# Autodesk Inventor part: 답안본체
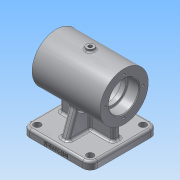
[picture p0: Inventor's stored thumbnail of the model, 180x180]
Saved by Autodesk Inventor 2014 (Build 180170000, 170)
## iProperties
Created: 2019-06
Part Number: 답안본체
Material: 알루미늄 6061
Document SubType Name: Modeling
Designer: NET
Density: 2.71 g/cm^3
Appearance: 알루미늄 - 평지
Mass: 612.698 g
Surface Area: 622.652 cm^2
Volume: 226.088 cm^3
Author: NET
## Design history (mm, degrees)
sketch "스케치1"
  geometry: L1 (45, 0)-(-45, 0); L2 (45, 0)-(45, 32); L3 (45, 32)-(-45, 32); L4 (-45, 32)-(-45, 0); L5 (45, 20)-(30.6, 20); L6 (30, 19.4)-(30, 17); L7 (30, 17)-(24, 17); L8 (24, 17)-(24, 22); L9 (21, 25)-(-21, 25); L10 (-24, 22)-(-24, 17); L11 (-24, 17)-(-30, 17); L12 (-30, 17)-(-30, 19.4); L13 (-30.6, 20)-(-45, 20); A1 r 0.6 centre (30.6, 19.4) between (30.6, 20) and (30, 19.4); A2 r 0.6 centre (-30.6, 19.4) between (-30, 19.4) and (-30.6, 20); A3 r 3 centre (21, 22) between (24, 22) and (21, 25); A4 r 3 centre (-21, 22) between (-21, 25) and (-24, 22); 5 further points
  constraints: 26 end point, 8 point on circle, 8 point on line, 8 tangent, 7 parallel, 5 perpendicular, 4 centre point, 2 equal radius, 1 coincident, 1 horizontal, 1 midpoint
  dimensions: "d0" = 90 distance of L1.start L1.end; "d1" = 64 diameter of L3 L1; "d2" = 48 distance of point (24, 25) point (-24, 25); "d3" = 50 diameter of L9 L1; "d4" = 15 distance of L5.start point (30, 20); "d5" = 40 diameter of L5 L1; "d6" = 34 diameter of L7 L1; "d7" = 6 distance of L6.end L7.end; "d8" = 6 distance of L10.end L11.end; "d9" = 34 diameter of L11 L1; "d10" = 40 diameter of L13 L1; "d11" = 0.6 radius of A1; "d12" = 3 radius of A3
revolve "회전1" sketch "스케치1" stored, may be unused: angle "d13" = 90 deg
chamfer "모따기1" distance "d14" = 1; stored, may be unused: second distance "d15" = 2, angle "d16" = 45 deg
node "작업 평면1"
sketch "스케치2"
  geometry: C1 r 5 at (0, 0); 1 further point
  constraints: 1 centre point, 1 coincident
  dimensions: "d18" = 10 diameter of C1
extrude "돌출1" join sketch "스케치2" stored distance "d19" = 10; taper "d20" = 0 deg
sketch "스케치3"
  geometry: C1 r 5 at (0, 0) reference; 1 further point
  constraints: 1 coincident
hole "구멍1" sketch "스케치3" at (0, 0) diameter "d21" = 4.917; stored, may be unused: countersink angle "d25" = 90 deg, drill point angle "d27" = 118 deg; dims "d22" = 6, "d23" = 4, "d24" = 2, "d26" = 20
fillet "모깎기1" dims "d28" = 2
node "작업 평면2"
sketch "스케치4"
  geometry: L1 (-45, -45)-(45, -45); L2 (45, -45)-(45, 45); L3 (45, 45)-(-45, 45); L4 (-45, 45)-(-45, -45); L5 (-45, -45)-(45, 45); L6 (45, -45)-(-45, 45); 1 further point
  constraints: 12 end point, 2 midpoint, 2 parallel, 1 horizontal, 1 perpendicular
  dimensions: "d30" = 90 distance of L2.end L3.end; "d31" = 90 distance of L1.end L2.end
extrude "돌출2" join sketch "스케치4" distance "d32" = 10; taper "d33" = 0 deg
fillet "모깎기2" dims "d34" = 10
fillet "모깎기3" dims "d35" = 3
sketch "스케치5"
  geometry: L1 (-35, -5)-(35, -5); L2 (35, -5)-(35, 5); L3 (35, 5)-(-35, 5); L4 (-35, 5)-(-35, -5); L5 (-35, -5)-(35, 5); L6 (35, -5)-(-35, 5); 1 further point
  constraints: 12 end point, 2 midpoint, 2 parallel, 1 horizontal, 1 perpendicular
  dimensions: "d36" = 10 distance between parallel lines of L3 L1; "d37" = 70 distance of L1.start L1.end
extrude "돌출3" join sketch "스케치5" stored distance "d38" = 10; taper "d39" = 0 deg
sketch "스케치6"
  geometry: L1 (45, -58)-(45, -65) reference; L2 (45, -65)-(-45, -65) reference; L3 (-45, -65)-(-45, -58) reference; L4 (-42, -55)-(-5, -55) reference; L5 (-5, -55)-(-5, -31.607) reference; L6 (-5, 33.272)-(-5, 35) reference; L7 (-5, 35)-(-2.458, 35) reference; L8 (-2.458, 35)-(-2.458, 24.879) reference; L9 (2.458, 24.879)-(2.458, 35) reference; L10 (2.458, 35)-(5, 35) reference; L11 (5, 35)-(5, 33.272) reference; L12 (5, -31.607)-(5, -55) reference; L13 (5, -55)-(42, -55) reference; L14 (-35, -55)-(-23.058, -22.189); A1 r 3 centre (42, -58) between (45, -58) and (42, -55) reference; A2 r 3 centre (-42, -58) between (-42, -55) and (-45, -58) reference; A3 r 32 centre (0, 0) between (-6.588, 31.314) and (-5, -31.607) reference; A4 r 25 centre (0, 0) between (-2.458, 24.879) and (2.458, 24.879) reference; A5 r 32 centre (0, 0) between (5, -31.607) and (6.588, 31.314) reference; 1 further point
  constraints: 2 end point, 1 point on circle, 1 point on line, 2 other
  dimensions: "d41" = 110 deg angle of L4 L14; "d42" = 10 distance from line of L14.start L3
feature "리브1" sketch "스케치6" dims "d43" = 1, "d44" = 10, "d45" = 0, "d46" = 0, "d47" = 1, "d48" = 1
fillet "모깎기4" dims "d49" = 3
fillet "모깎기5" dims "d50" = 3
fillet "모깎기6" dims "d51" = 3
fillet "모깎기7" dims "d52" = 3
fillet "모깎기8" dims "d53" = 3
fillet "모깎기9" dims "d54" = 3
fillet "모깎기10" dims "d55" = 3
fillet "모깎기11" dims "d56" = 3
fillet "모깎기12" dims "d57" = 3
sketch "스케치7"
  geometry: C1 r 4.5 at (-35, 35); C2 r 4.5 at (-35, -35); A1 r 7 centre (-35, 35) between (-35, 42) and (-42, 35) reference; A2 r 7 centre (-35, -35) between (-42, -35) and (-35, -42) reference; 1 further point
  constraints: 2 centre point, 2 coincident
  dimensions: "d58" = 9 diameter of C1; "d59" = 9 diameter of C2
extrude "돌출4" cut sketch "스케치7" distance "d60" = 35; taper "d61" = 0 deg
sketch "스케치8"
  geometry: C1 r 32 at (0, 0) reference; 1 further point
  constraints: 1 horizontal alignment
  dimensions: "d63" = 25 distance of C1.centre point (-25, 0)
hole "구멍2" sketch "스케치8" at (-25, 0) diameter "d64" = 3.242; stored, may be unused: countersink angle "d68" = 90 deg, drill point angle "d70" = 118 deg; dims "d65" = 7, "d66" = 4, "d67" = 2, "d69" = 9
sketch "스케치9"
  geometry: L1 (0, 0)-(70, 0) reference; L2 (-10, 7)-(-10, 0) reference; 2 further points
  constraints: 1 other
  dimensions: "d74" = 4 distance from line of point (35, 4) L1; "d75" = 45 distance from line of point (35, 4) L2
feature "엠보싱1" sketch "스케치9" dims "d0" = 90, "d1" = 64, "d2" = 48, "d3" = 50, "d4" = 15, "d5" = 40, "d6" = 34, "d7" = 6, "d8" = 6, "d9" = 34, "d10" = 40, "d11" = 0.6, "d12" = 3, "d76" = 0.5, "d77" = 0
sketch "스케치10" dims "d80" = 20
  geometry: L1 (35, -45)-(-35, -45) reference; L2 (45, 35)-(45, -35) reference; L3 (-22, -40)-(22, -40); L4 (40, -22)-(40, 22); L5 (-40, 22)-(-40, -22); L6 (-40, -40)-(40, 40); L7 (40, -40)-(-40, 40); L8 (-25, -37)-(-25, -35); L9 (-37, -25)-(-35, -25); L10 (-37, 25)-(-35, 25); L11 (-25, 35)-(-25, 37); L12 (22, 40)-(-22, 40); L13 (-26.34, 40)-(-40, 40); L14 (25, 37)-(25, 35); L15 (35, 25)-(37, 25); L16 (25, -37)-(25, -35); L17 (35, -25)-(37, -25); C1 r 10 at (35, 35); C2 r 10 at (-35, -35); C3 r 10 at (35, -35); A1 r 10 centre (35, -35) between (35, -45) and (45, -35) reference; A2 r 10 centre (35, 35) between (45, 35) and (35, 45) reference; A3 r 10 centre (-35, 35) between (-35, 45) and (-45, 35) reference; A4 r 10 centre (-35, -35) between (-45, -35) and (-35, -45) reference; A5 r 10 centre (-35, 35) between (-35, 25) and (-25, 35); A6 r 10 centre (35, 35) between (25, 35) and (35, 25); A7 r 10 centre (35, -35) between (35, -25) and (25, -35); A8 r 10 centre (-35, -35) between (-25, -35) and (-35, -25); A9 r 3 centre (-37, -22) between (-40, -22) and (-37, -25); A10 r 3 centre (-22, -37) between (-25, -37) and (-22, -40); A11 r 3 centre (37, 22) between (40, 22) and (37, 25); A12 r 3 centre (22, 37) between (25, 37) and (22, 40); A13 r 3 centre (-37, 22) between (-37, 25) and (-40, 22); A14 r 3 centre (-22, 37) between (-22, 40) and (-25, 37); A15 r 3 centre (37, -22) between (37, -25) and (40, -22); A16 r 3 centre (22, -37) between (22, -40) and (25, -37); 3 further points
  constraints: 30 end point, 30 tangent, 24 point on circle, 15 centre point, 8 perpendicular, 5 parallel, 5 point on line, 4 coincident, 3 equal radius, 2 horizontal, 2 midpoint, 1 vertical, 3 other
  dimensions: "d78" = 80 distance of L6.end L7.end; "d79" = 80 distance of L7.start L6.end; "d81" = 20 diameter of C1; "d82" = 20 diameter of C2; "d83" = 20 diameter of C3; "d85" = 10 radius of A5; "d86" = 3 radius of A9; "d87" = 3 radius of A10; "d88" = 3 radius of A11; "d89" = 3 radius of A12; "d90" = 3 radius of A13; "d91" = 3 radius of A14; "d92" = 3 radius of A15; "d93" = 3 radius of A16; "d94" = 5 distance between parallel lines of L2 L4; "d95" = 85 distance between parallel lines of L2 L5; "d96" = 85 distance between parallel lines of L1 L12; "d97" = 85 distance from line of L6.start L2
extrude "돌출5" cut sketch "스케치10" distance "d98" = 5; taper "d99" = 0 deg
node "솔리드1"
mirror "대칭1"
mirror "대칭2"
pattern_circular "원형 패턴1" dims angle "d72" = 360 deg
mirror "대칭3"
node "절단 모서리 투영1"
other parameters: "d17" = 35, "d29" = -65
